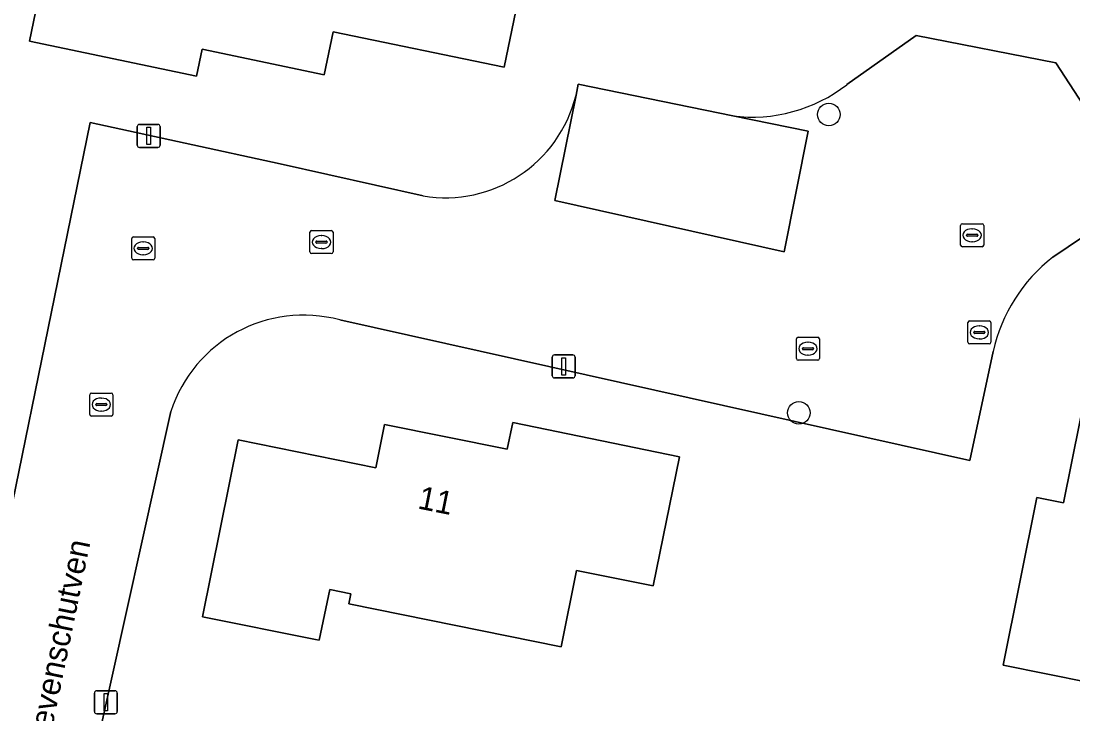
# Model space of a CAD drawing. Extents: x 163426 to 164192, y 380329 to 381641.
# Drawn here: x 163640.94 to 163686.54, y 381532.46 to 381562.48 of the extents above; entities that cross this region are included whole.
import ezdxf

# ---------------------------------------------------------------- set-up
doc = ezdxf.new("R2010")
doc.units = 0
for name, color, linetype in [('IMGEO_Boom', 7, 'Continuous'), ('IMGEO_Brandkraan', 7, 'Continuous'), ('IMGEO_Erf', 7, 'Continuous'), ('IMGEO_Kolk', 7, 'Continuous'), ('IMGEO_Lichtmast', 7, 'Continuous'), ('IMGEO_Openbare_ruimte_label', 7, 'Continuous'), ('IMGEO_Pand', 7, 'Continuous'), ('IMGEO_Pand_nummerreeks', 7, 'Continuous'), ('IMGEO_Parkeervlak_open', 7, 'Continuous'), ('IMGEO_Rijbaan_lokaal_open', 7, 'Continuous'), ('IMGEO_Rioolput', 7, 'Continuous')]:
    doc.layers.add(name, color=color, linetype=linetype)

msp = doc.modelspace()

# ---------------------------------------------------------------- linework, layer by layer
at = {"layer": 'IMGEO_Boom'}
for centre in [(163675.966, 381558.43), (163674.659, 381545.509)]:
    msp.add_circle(centre, 0.489, dxfattribs=at)
at = {"layer": 'IMGEO_Brandkraan'}
for p, q in [((163681.986, 381548.564), (163681.986, 381549.416)), ((163682.061, 381549.49), (163682.913, 381549.49)), ((163682.474, 381549.27), (163682.499, 381549.27)), ((163682.987, 381549.416), (163682.987, 381548.564)), ((163682.245, 381548.984), (163682.245, 381548.996)), ((163682.683, 381548.947), (163682.285, 381548.947)), ((163682.288, 381549.033), (163682.686, 381549.033)), ((163682.497, 381548.71), (163682.472, 381548.71)), ((163682.729, 381548.996), (163682.729, 381548.984)), ((163682.913, 381548.49), (163682.061, 381548.49))]:
    msp.add_line(p, q, dxfattribs=at)
for points in [[(163681.986, 381548.564), (163681.986, 381549.416)], [(163682.061, 381549.49), (163682.913, 381549.49)], [(163682.987, 381549.416), (163682.987, 381548.564)], [(163682.913, 381548.49), (163682.061, 381548.49)]]:
    msp.add_lwpolyline(points, dxfattribs=at)
for centre, radius, start, end in [((163682.063, 381549.414), 0.0765, 91.552, 178.448), ((163682.063, 381549.414), 0.0765, 91.552, 178.448), ((163682.911, 381549.414), 0.0765, 1.552, 88.448), ((163682.911, 381549.414), 0.0765, 1.552, 88.448), ((163682.285, 381548.993), 0.0403, 85.8775, 175.7526), ((163682.282, 381548.983), 0.0366, 178.938, 274.7102), ((163682.686, 381548.99), 0.043, 264.8664, 352.4533), ((163682.69, 381548.995), 0.0386, 1.7309, 96.639), ((163682.063, 381548.566), 0.0765, 181.552, 268.448), ((163682.063, 381548.566), 0.0765, 181.552, 268.448), ((163682.911, 381548.566), 0.0765, 271.552, 358.448), ((163682.911, 381548.566), 0.0765, 271.552, 358.448)]:
    msp.add_arc(centre, radius, start, end, dxfattribs=at)
for centre, major_axis, ratio, start_param, end_param in [((163682.473, 381548.99), (-0.387, 0.002), 0.722429, 4.712389, 7.853982), ((163682.498, 381548.99), (-0.39, 0.002), 0.717154, 1.570796, 4.712389)]:
    msp.add_ellipse(centre, major_axis=major_axis, ratio=ratio, start_param=start_param, end_param=end_param, dxfattribs=at)
at = {"layer": 'IMGEO_Erf'}
for points in [[(163661.881, 381560.489), (163654.472, 381562.021), (163654.087, 381560.149), (163648.795, 381561.256), (163648.551, 381560.092), (163641.305, 381561.605), (163642.325, 381566.5), (163642.468, 381567.186), (163645.798, 381566.491), (163646.478, 381569.826), (163655.694, 381567.913), (163655.596, 381567.443), (163656.517, 381567.252), (163656.978, 381569.475), (163663.466, 381568.137), (163662.896, 381565.385)], [(163697.719, 381549.975), (163696.896, 381545.888), (163694.694, 381546.332), (163694.509, 381545.412), (163694.969, 381545.32), (163693.115, 381536.132), (163689.782, 381536.784), (163689.113, 381533.453), (163683.515, 381534.572), (163684.976, 381541.843), (163686.14, 381541.612), (163687.206, 381546.909), (163689.083, 381546.527), (163690.093, 381551.524)], [(163662.012, 381543.927), (163662.258, 381545.085), (163669.494, 381543.595), (163668.351, 381538.013), (163665.022, 381538.677), (163664.354, 381535.361), (163655.148, 381537.225), (163655.238, 381537.662), (163654.324, 381537.85), (163653.873, 381535.653), (163653.712, 381535.685), (163648.81, 381536.673), (163650.359, 381544.336), (163656.322, 381543.117), (163656.706, 381544.997)]]:
    msp.add_lwpolyline(points, close=True, dxfattribs=at)
for points in [[(163676.737, 381559.725), (163679.748, 381561.858), (163685.801, 381560.676), (163689.568, 381554.874), (163685.674, 381552.248)], [(163665.001, 381559.265), (163665.098, 381559.741), (163671.793, 381558.373)], [(163638.862, 381532.644), (163638.733, 381532.691), (163643.944, 381558.087), (163652.179, 381556.3), (163658.369, 381554.907)], [(163683.088, 381548.17), (163682.067, 381543.435), (163654.763, 381549.531)], [(163647.434, 381545.567), (163644.279, 381531.292)]]:
    msp.add_lwpolyline(points, dxfattribs=at)
for centre, radius, start, end in [((163672.638, 381564.999), 6.68, 262.7348, 307.8539), ((163659.336, 381560.661), 5.835, 260.4642, 346.155), ((163690.009, 381546.64), 7.088, 127.7037, 167.5359), ((163653.189, 381543.684), 6.055, 74.9307, 161.8841)]:
    msp.add_arc(centre, radius, start, end, dxfattribs=at)
at = {"layer": 'IMGEO_Kolk'}
for p, q in [((163653.466, 381552.478), (163653.466, 381553.33)), ((163653.541, 381553.404), (163654.393, 381553.404)), ((163653.954, 381553.184), (163653.979, 381553.184)), ((163654.467, 381553.33), (163654.467, 381552.478)), ((163653.725, 381552.898), (163653.725, 381552.91)), ((163654.163, 381552.861), (163653.765, 381552.861)), ((163653.768, 381552.947), (163654.166, 381552.947)), ((163654.209, 381552.91), (163654.209, 381552.898)), ((163654.393, 381552.404), (163653.541, 381552.404)), ((163653.977, 381552.624), (163653.952, 381552.624)), ((163674.556, 381547.859), (163674.556, 381548.711)), ((163674.631, 381548.785), (163675.483, 381548.785)), ((163675.557, 381548.711), (163675.557, 381547.859)), ((163674.815, 381548.279), (163674.815, 381548.291)), ((163675.253, 381548.242), (163674.855, 381548.242)), ((163674.858, 381548.328), (163675.256, 381548.328)), ((163675.044, 381548.565), (163675.069, 381548.565)), ((163675.299, 381548.291), (163675.299, 381548.279)), ((163675.483, 381547.785), (163674.631, 381547.785)), ((163675.067, 381548.005), (163675.042, 381548.005)), ((163643.997, 381546.365), (163644.849, 381546.365)), ((163643.922, 381545.439), (163643.922, 381546.291)), ((163644.224, 381545.908), (163644.622, 381545.908)), ((163644.41, 381546.145), (163644.435, 381546.145)), ((163644.923, 381546.291), (163644.923, 381545.439)), ((163644.181, 381545.859), (163644.181, 381545.871)), ((163644.619, 381545.822), (163644.221, 381545.822)), ((163644.433, 381545.585), (163644.408, 381545.585)), ((163644.665, 381545.871), (163644.665, 381545.859)), ((163644.849, 381545.365), (163643.997, 381545.365))]:
    msp.add_line(p, q, dxfattribs=at)
for points in [[(163653.466, 381552.478), (163653.466, 381553.33)], [(163653.541, 381553.404), (163654.393, 381553.404)], [(163654.467, 381553.33), (163654.467, 381552.478)], [(163654.393, 381552.404), (163653.541, 381552.404)], [(163674.556, 381547.859), (163674.556, 381548.711)], [(163674.631, 381548.785), (163675.483, 381548.785)], [(163675.557, 381548.711), (163675.557, 381547.859)], [(163675.483, 381547.785), (163674.631, 381547.785)], [(163643.997, 381546.365), (163644.849, 381546.365)], [(163643.922, 381545.439), (163643.922, 381546.291)], [(163644.923, 381546.291), (163644.923, 381545.439)], [(163644.849, 381545.365), (163643.997, 381545.365)]]:
    msp.add_lwpolyline(points, dxfattribs=at)
for centre, radius, start, end in [((163653.543, 381553.328), 0.0765, 91.552, 178.448), ((163653.543, 381553.328), 0.0765, 91.552, 178.448), ((163654.391, 381553.328), 0.0765, 1.552, 88.448), ((163654.391, 381553.328), 0.0765, 1.552, 88.448), ((163653.765, 381552.907), 0.0403, 85.8775, 175.7526), ((163653.762, 381552.897), 0.0366, 178.938, 274.7102), ((163654.166, 381552.904), 0.043, 264.8664, 352.4533), ((163654.17, 381552.909), 0.0386, 1.7309, 96.639), ((163653.543, 381552.48), 0.0765, 181.552, 268.448), ((163653.543, 381552.48), 0.0765, 181.552, 268.448), ((163654.391, 381552.48), 0.0765, 271.552, 358.448), ((163654.391, 381552.48), 0.0765, 271.552, 358.448), ((163674.633, 381548.709), 0.0765, 91.552, 178.448), ((163674.633, 381548.709), 0.0765, 91.552, 178.448), ((163675.481, 381548.709), 0.0765, 1.552, 88.448), ((163675.481, 381548.709), 0.0765, 1.552, 88.448), ((163674.855, 381548.288), 0.0403, 85.8775, 175.7526), ((163674.852, 381548.278), 0.0366, 178.938, 274.7102), ((163675.256, 381548.285), 0.043, 264.8664, 352.4533), ((163675.26, 381548.29), 0.0386, 1.7309, 96.639), ((163674.633, 381547.861), 0.0765, 181.552, 268.448), ((163674.633, 381547.861), 0.0765, 181.552, 268.448), ((163675.481, 381547.861), 0.0765, 271.552, 358.448), ((163675.481, 381547.861), 0.0765, 271.552, 358.448), ((163643.999, 381546.289), 0.0765, 91.552, 178.448), ((163643.999, 381546.289), 0.0765, 91.552, 178.448), ((163644.847, 381546.289), 0.0765, 1.552, 88.448), ((163644.847, 381546.289), 0.0765, 1.552, 88.448), ((163644.221, 381545.868), 0.0403, 85.8775, 175.7526), ((163644.626, 381545.87), 0.0386, 1.7309, 96.639), ((163643.999, 381545.441), 0.0765, 181.552, 268.448), ((163643.999, 381545.441), 0.0765, 181.552, 268.448), ((163644.218, 381545.858), 0.0366, 178.938, 274.7102), ((163644.622, 381545.865), 0.043, 264.8664, 352.4533), ((163644.847, 381545.441), 0.0765, 271.552, 358.448), ((163644.847, 381545.441), 0.0765, 271.552, 358.448)]:
    msp.add_arc(centre, radius, start, end, dxfattribs=at)
for centre, major_axis, ratio, start_param, end_param in [((163653.953, 381552.904), (-0.387, 0.002), 0.722429, 4.712389, 7.853982), ((163653.978, 381552.904), (-0.39, 0.002), 0.717154, 1.570796, 4.712389), ((163675.043, 381548.285), (-0.387, 0.002), 0.722429, 4.712389, 7.853982), ((163675.068, 381548.285), (-0.39, 0.002), 0.717154, 1.570796, 4.712389), ((163644.409, 381545.865), (-0.387, 0.002), 0.722429, 4.712389, 7.853982), ((163644.434, 381545.865), (-0.39, 0.002), 0.717154, 1.570796, 4.712389)]:
    msp.add_ellipse(centre, major_axis=major_axis, ratio=ratio, start_param=start_param, end_param=end_param, dxfattribs=at)
at = {"layer": 'IMGEO_Lichtmast'}
for p, q in [((163645.978, 381557.106), (163645.978, 381557.906)), ((163645.978, 381557.906), (163645.978, 381557.106)), ((163646.078, 381558.006), (163646.868, 381558.006)), ((163646.868, 381558.006), (163646.078, 381558.006)), ((163646.968, 381557.906), (163646.968, 381557.106)), ((163646.968, 381557.106), (163646.968, 381557.906)), ((163646.868, 381557.006), (163646.078, 381557.006)), ((163646.078, 381557.006), (163646.868, 381557.006)), ((163663.97, 381547.116), (163663.97, 381547.916)), ((163663.97, 381547.916), (163663.97, 381547.116)), ((163664.07, 381548.016), (163664.86, 381548.016)), ((163664.86, 381548.016), (163664.07, 381548.016)), ((163664.96, 381547.916), (163664.96, 381547.116)), ((163664.96, 381547.116), (163664.96, 381547.916)), ((163664.86, 381547.016), (163664.07, 381547.016)), ((163664.07, 381547.016), (163664.86, 381547.016)), ((163644.122, 381532.567), (163644.122, 381533.367)), ((163644.122, 381533.367), (163644.122, 381532.567)), ((163644.222, 381533.467), (163645.012, 381533.467)), ((163645.012, 381533.467), (163644.222, 381533.467)), ((163645.112, 381533.367), (163645.112, 381532.567)), ((163645.112, 381532.567), (163645.112, 381533.367)), ((163645.012, 381532.467), (163644.222, 381532.467)), ((163644.222, 381532.467), (163645.012, 381532.467))]:
    msp.add_line(p, q, dxfattribs=at)
for points in [[(163646.398, 381557.881), (163646.548, 381557.881), (163646.548, 381557.131), (163646.398, 381557.131), (163646.398, 381557.881)], [(163664.39, 381547.891), (163664.54, 381547.891), (163664.54, 381547.141), (163664.39, 381547.141), (163664.39, 381547.891)], [(163644.542, 381533.342), (163644.692, 381533.342), (163644.692, 381532.592), (163644.542, 381532.592), (163644.542, 381533.342)]]:
    msp.add_lwpolyline(points, dxfattribs=at)
for centre, start, end in [((163646.078, 381557.906), 90, 180), ((163646.078, 381557.906), 90, 180), ((163646.868, 381557.906), 0, 90), ((163646.868, 381557.906), 360, 90), ((163646.078, 381557.106), 180, 270), ((163646.078, 381557.106), 180, 270), ((163646.868, 381557.106), 270, 0), ((163646.868, 381557.106), 270, 0), ((163664.07, 381547.916), 90, 180), ((163664.07, 381547.916), 90, 180), ((163664.86, 381547.916), 0, 90), ((163664.86, 381547.916), 360, 90), ((163664.07, 381547.116), 180, 270), ((163664.07, 381547.116), 180, 270), ((163664.86, 381547.116), 270, 0), ((163664.86, 381547.116), 270, 0), ((163644.222, 381533.367), 90, 180), ((163644.222, 381533.367), 90, 180), ((163645.012, 381533.367), 0, 90), ((163645.012, 381533.367), 360, 90), ((163644.222, 381532.567), 180, 270), ((163644.222, 381532.567), 180, 270), ((163645.012, 381532.567), 270, 0), ((163645.012, 381532.567), 270, 0)]:
    msp.add_arc(centre, 0.1, start, end, dxfattribs=at)
at = {"layer": 'IMGEO_Pand'}
for points in [[(163648.551, 381560.092), (163648.795, 381561.256), (163654.087, 381560.149), (163654.472, 381562.021), (163661.881, 381560.489), (163662.896, 381565.385), (163663.466, 381568.137), (163656.978, 381569.475), (163656.517, 381567.252), (163655.596, 381567.443), (163655.694, 381567.913), (163646.478, 381569.826), (163645.798, 381566.491), (163642.468, 381567.186), (163642.325, 381566.5), (163641.305, 381561.605)], [(163689.113, 381533.453), (163689.782, 381536.784), (163693.115, 381536.132), (163694.969, 381545.32), (163694.509, 381545.412), (163694.694, 381546.332), (163696.896, 381545.888), (163697.719, 381549.975), (163690.093, 381551.524), (163689.083, 381546.527), (163687.206, 381546.909), (163686.14, 381541.612), (163684.976, 381541.843), (163683.515, 381534.572)], [(163664.354, 381535.361), (163665.022, 381538.677), (163668.351, 381538.013), (163669.494, 381543.595), (163662.258, 381545.085), (163662.012, 381543.927), (163656.706, 381544.997), (163656.322, 381543.117), (163650.359, 381544.336), (163648.81, 381536.673), (163653.712, 381535.685), (163653.873, 381535.653), (163654.324, 381537.85), (163655.238, 381537.662), (163655.148, 381537.225)]]:
    msp.add_lwpolyline(points, close=True, dxfattribs=at)
at = {"layer": 'IMGEO_Parkeervlak_open'}
msp.add_lwpolyline([(163665.001, 381559.265), (163664.077, 381554.708), (163674.023, 381552.486), (163675.063, 381557.705), (163671.793, 381558.373), (163665.098, 381559.741)], close=True, dxfattribs=at)
at = {"layer": 'IMGEO_Rijbaan_lokaal_open'}
for points in [[(163685.674, 381552.248), (163689.568, 381554.874), (163685.801, 381560.676), (163679.748, 381561.858), (163676.737, 381559.725)], [(163671.793, 381558.373), (163675.063, 381557.705), (163674.023, 381552.486), (163664.077, 381554.708), (163665.001, 381559.265)], [(163658.369, 381554.907), (163652.179, 381556.3), (163643.944, 381558.087), (163638.733, 381532.691), (163638.862, 381532.644)], [(163654.763, 381549.531), (163682.067, 381543.435), (163683.088, 381548.17)], [(163644.279, 381531.292), (163647.434, 381545.567)]]:
    msp.add_lwpolyline(points, dxfattribs=at)
for centre, radius, start, end in [((163672.638, 381564.999), 6.68, 262.7348, 307.8539), ((163659.336, 381560.661), 5.835, 260.4642, 346.155), ((163690.009, 381546.64), 7.088, 127.7037, 167.5359), ((163653.189, 381543.684), 6.055, 74.9307, 161.8841)]:
    msp.add_arc(centre, radius, start, end, dxfattribs=at)
at = {"layer": 'IMGEO_Rioolput'}
for p, q in [((163681.751, 381553.7), (163682.603, 381553.7)), ((163681.676, 381552.774), (163681.676, 381553.626)), ((163681.935, 381553.194), (163681.935, 381553.206)), ((163681.978, 381553.243), (163682.376, 381553.243)), ((163682.164, 381553.48), (163682.189, 381553.48)), ((163682.419, 381553.206), (163682.419, 381553.194)), ((163682.677, 381553.626), (163682.677, 381552.774)), ((163645.739, 381552.206), (163645.739, 381553.058)), ((163645.814, 381553.132), (163646.666, 381553.132)), ((163646.227, 381552.912), (163646.252, 381552.912)), ((163646.74, 381553.058), (163646.74, 381552.206)), ((163682.373, 381553.157), (163681.975, 381553.157)), ((163682.187, 381552.92), (163682.162, 381552.92)), ((163645.998, 381552.626), (163645.998, 381552.638)), ((163646.436, 381552.589), (163646.038, 381552.589)), ((163646.041, 381552.675), (163646.439, 381552.675)), ((163646.25, 381552.352), (163646.225, 381552.352)), ((163646.482, 381552.638), (163646.482, 381552.626)), ((163682.603, 381552.7), (163681.751, 381552.7)), ((163646.666, 381552.132), (163645.814, 381552.132))]:
    msp.add_line(p, q, dxfattribs=at)
for points in [[(163681.751, 381553.7), (163682.603, 381553.7)], [(163681.676, 381552.774), (163681.676, 381553.626)], [(163682.677, 381553.626), (163682.677, 381552.774)], [(163645.739, 381552.206), (163645.739, 381553.058)], [(163645.814, 381553.132), (163646.666, 381553.132)], [(163646.74, 381553.058), (163646.74, 381552.206)], [(163682.603, 381552.7), (163681.751, 381552.7)], [(163646.666, 381552.132), (163645.814, 381552.132)]]:
    msp.add_lwpolyline(points, dxfattribs=at)
for centre, radius, start, end in [((163681.753, 381553.624), 0.0765, 91.552, 178.448), ((163681.753, 381553.624), 0.0765, 91.552, 178.448), ((163682.601, 381553.624), 0.0765, 1.552, 88.448), ((163682.601, 381553.624), 0.0765, 1.552, 88.448), ((163681.975, 381553.203), 0.0403, 85.8775, 175.7526), ((163681.972, 381553.193), 0.0366, 178.938, 274.7102), ((163682.376, 381553.2), 0.043, 264.8664, 352.4533), ((163682.38, 381553.205), 0.0386, 1.7309, 96.639), ((163645.816, 381553.056), 0.0765, 91.552, 178.448), ((163645.816, 381553.056), 0.0765, 91.552, 178.448), ((163646.664, 381553.056), 0.0765, 1.552, 88.448), ((163646.664, 381553.056), 0.0765, 1.552, 88.448), ((163681.753, 381552.776), 0.0765, 181.552, 268.448), ((163681.753, 381552.776), 0.0765, 181.552, 268.448), ((163682.601, 381552.776), 0.0765, 271.552, 358.448), ((163682.601, 381552.776), 0.0765, 271.552, 358.448), ((163646.038, 381552.635), 0.0403, 85.8775, 175.7526), ((163646.035, 381552.625), 0.0366, 178.938, 274.7102), ((163646.439, 381552.632), 0.043, 264.8664, 352.4533), ((163646.443, 381552.637), 0.0386, 1.7309, 96.639), ((163645.816, 381552.208), 0.0765, 181.552, 268.448), ((163645.816, 381552.208), 0.0765, 181.552, 268.448), ((163646.664, 381552.208), 0.0765, 271.552, 358.448), ((163646.664, 381552.208), 0.0765, 271.552, 358.448)]:
    msp.add_arc(centre, radius, start, end, dxfattribs=at)
for centre, major_axis, ratio, start_param, end_param in [((163682.163, 381553.2), (-0.387, 0.002), 0.722429, 4.712389, 7.853982), ((163682.188, 381553.2), (-0.39, 0.002), 0.717154, 1.570796, 4.712389), ((163646.226, 381552.632), (-0.387, 0.002), 0.722429, 4.712389, 7.853982), ((163646.251, 381552.632), (-0.39, 0.002), 0.717154, 1.570796, 4.712389)]:
    msp.add_ellipse(centre, major_axis=major_axis, ratio=ratio, start_param=start_param, end_param=end_param, dxfattribs=at)

# ---------------------------------------------------------------- texts
at = {"layer": 'IMGEO_Openbare_ruimte_label'}
msp.add_text('Grevenschutven', height=1, rotation=78.4093, dxfattribs=at).set_placement((163641.996, 381530.358))
at = {"layer": 'IMGEO_Pand_nummerreeks'}
msp.add_text('11', height=1, rotation=348.5987, dxfattribs=at).set_placement((163658.102, 381541.37))

doc.saveas('drawing.dxf')
